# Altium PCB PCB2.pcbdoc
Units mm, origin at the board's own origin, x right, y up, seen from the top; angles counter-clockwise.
Board outline 165.99 x 69.13 mm, 2 copper layers (Top Layer, Bottom Layer); 50 components, 27 nets, 130 pads, 0 vias.
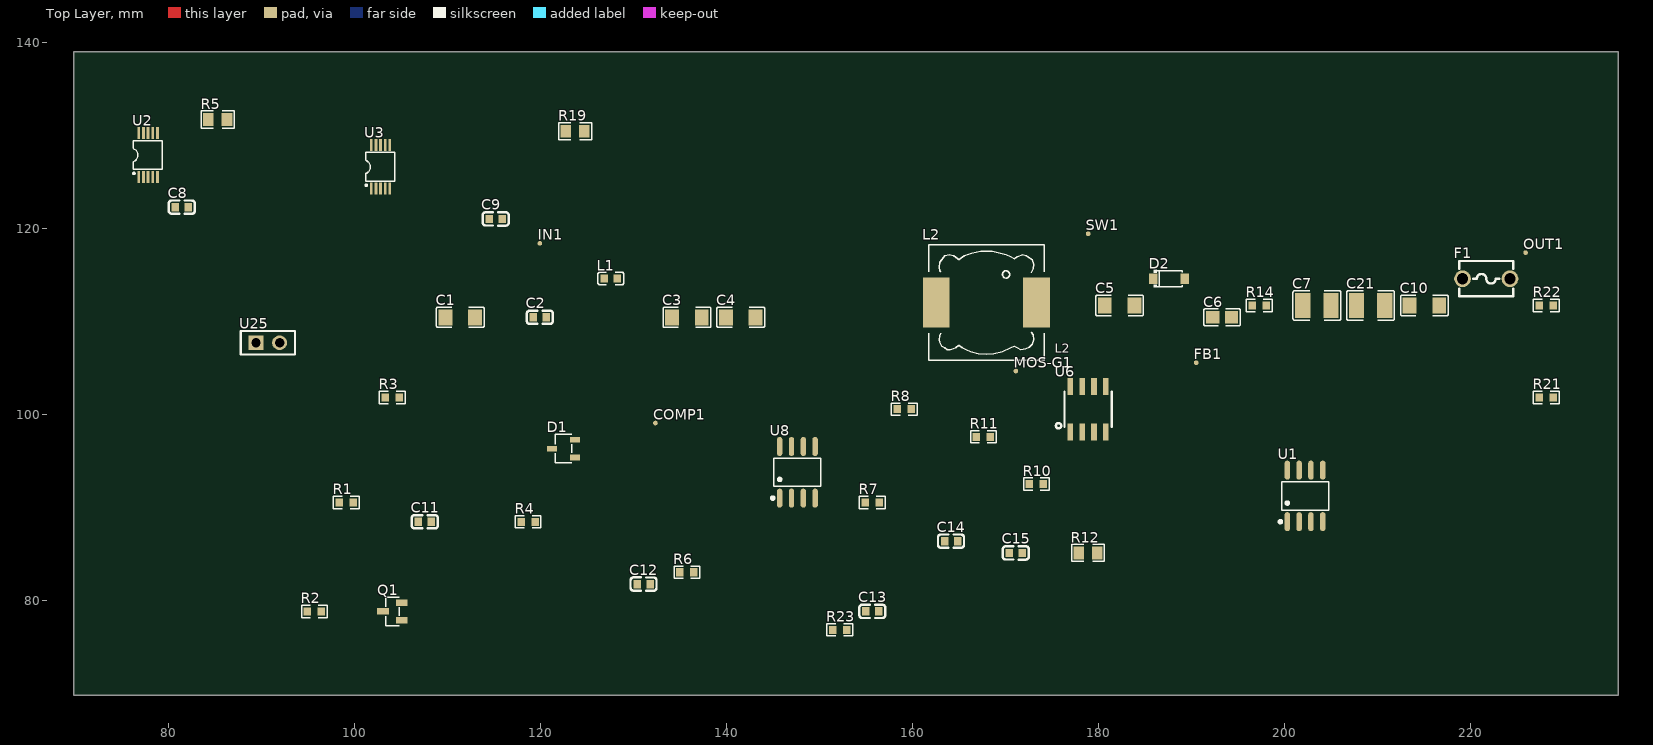
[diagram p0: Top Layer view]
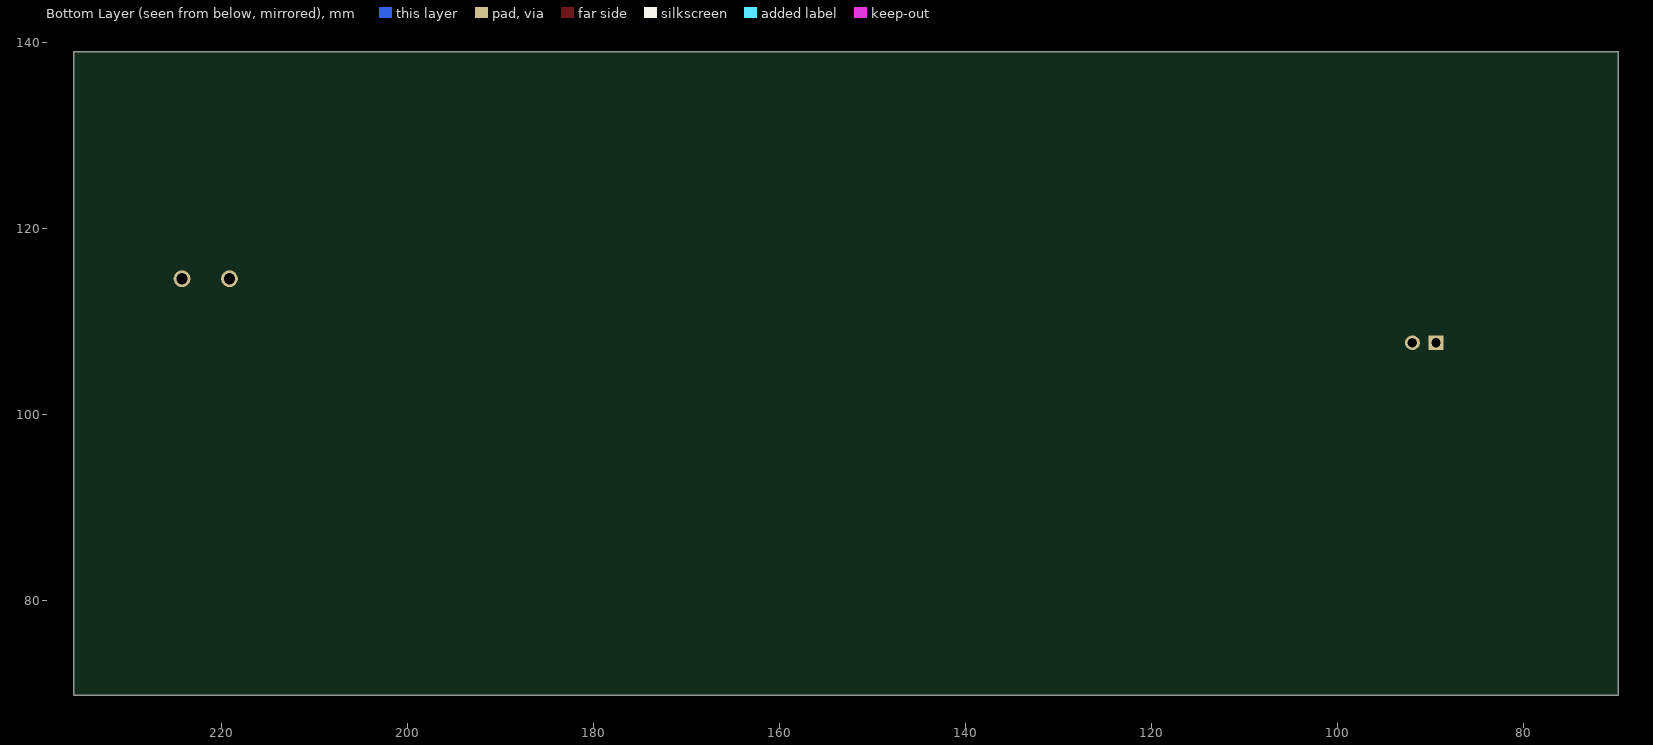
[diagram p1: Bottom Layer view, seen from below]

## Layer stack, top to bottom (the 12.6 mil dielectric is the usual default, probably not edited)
Top Layer: signal copper (thickness not stored)
Dielectric: dielectric 0.32, FR-4, Dk 4.8
Bottom Layer: signal copper (thickness not stored)

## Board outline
235.837,69.85 69.85,69.85 69.85,138.978 235.837,138.978

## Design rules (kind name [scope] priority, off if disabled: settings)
BoardOutlineClearance copperThickness1oz [All] p0: genericclearance=0.254 ignorepadtopadclearanceinfootprint=FALSE except(0: Arc-SplitContinuation Track-SplitContinuation SMDPad-SplitContinuation THPad-SplitContinuation Via-SplitContinuation Fill-SplitContinuation Poly-SplitContinuation Region-SplitContinuation Text-SplitContinuation; 0.152: SMDPad-CutoutEdge THPad-CutoutEdge Via-CutoutEdge Fill-CutoutEdge Region-CutoutEdge; 0.3: Track-OutlineEdge SMDPad-OutlineEdge THPad-OutlineEdge Via-OutlineEdge Fill-OutlineEdge Region-OutlineEdge Poly-OutlineEdge Text-OutlineEdge Track-CutoutEdge)
BoardOutlineClearance copperThickness2oz [All] p0: genericclearance=0.254 ignorepadtopadclearanceinfootprint=FALSE except(0: Arc-SplitContinuation Track-SplitContinuation SMDPad-SplitContinuation THPad-SplitContinuation Via-SplitContinuation Fill-SplitContinuation Poly-SplitContinuation Region-SplitContinuation Text-SplitContinuation; 0.152: SMDPad-CutoutEdge THPad-CutoutEdge Via-CutoutEdge Fill-CutoutEdge Region-CutoutEdge; 0.3: Track-OutlineEdge SMDPad-OutlineEdge THPad-OutlineEdge Via-OutlineEdge Fill-OutlineEdge Region-OutlineEdge Poly-OutlineEdge Text-OutlineEdge Track-CutoutEdge)
Clearance copperThickness1oz [(InNet('SPI_CS') OR InNet('SPI_CLK') OR InNet('SPI_SI') OR InNet('GND') OR InNet('5V') OR InNet('$1N3770') OR InNet('$1N3760') OR InNet('VBUS') OR InNet('170_GND') OR InNet('$1N2831') OR InNet('$1N2825') OR InNet('$1N2828') OR InNet('170V') OR InNet('$1N2851') OR InNet('$1N3400') OR InNet('$1N2845') OR InNet('$1N2846') OR InNet('$1N3681') OR InNet('$1N2823') OR InNet('$1N2833') OR InNet('$1N2832') OR InNet('$1N2815') OR InNet('$1N2826') OR InNet('POWER') OR InNet('17V') OR InNet('SDA') OR InNet('SCL'))] p1: gap=0.178 ignorepadtopadclearanceinfootprint=FALSE except(0.102: Track-Track; 0.152: Track-SMDPad SMDPad-SMDPad Track-THPad SMDPad-THPad THPad-THPad Track-Via SMDPad-Via THPad-Via Via-Via Track-Fill SMDPad-Fill THPad-Fill Via-Fill Fill-Fill SMDPad-Region THPad-Region Via-Region Fill-Region Region-Region Track-Poly SMDPad-Poly THPad-Poly Via-Poly Fill-Poly Poly-Poly Track-Text SMDPad-Text THPad-Text Via-Text Fill-Text Region-Text Poly-Text Text-Text Track-Hole SMDPad-Hole THPad-Hole Via-Hole Fill-Hole Region-Hole Poly-Hole Text-Hole; 0.3: Track-Region Region-Poly Track-Sheet SMDPad-Sheet THPad-Sheet Via-Sheet Fill-Sheet Region-Sheet Poly-Sheet Text-Sheet Sheet-Hole)
Clearance copperThickness2oz [All] p1: gap=0.178 ignorepadtopadclearanceinfootprint=FALSE except(0.152: Track-SMDPad SMDPad-SMDPad Track-THPad SMDPad-THPad THPad-THPad Track-Via SMDPad-Via THPad-Via Via-Via Track-Fill SMDPad-Fill THPad-Fill Via-Fill Fill-Fill SMDPad-Region THPad-Region Via-Region Fill-Region Region-Region Track-Poly SMDPad-Poly THPad-Poly Via-Poly Fill-Poly Poly-Poly Track-Text SMDPad-Text THPad-Text Via-Text Fill-Text Region-Text Poly-Text Text-Text Track-Hole SMDPad-Hole THPad-Hole Via-Hole Fill-Hole Region-Hole Poly-Hole Text-Hole; 0.203: Track-Track; 0.3: Track-Region Region-Poly Track-Sheet SMDPad-Sheet THPad-Sheet Via-Sheet Fill-Sheet Region-Sheet Poly-Sheet Text-Sheet Sheet-Hole)
DiffPairsRouting differentialPair [All] p1: maxuncoupledlength=10 minlimit=6 maxlimit=6 mostfreqgap=6 toplayer_minwidth=5 toplayer_prefwidth=10 toplayer_maxwidth=100 bottomlayer_minwidth=5 bottomlayer_prefwidth=10 bottomlayer_maxwidth=100
PasteMaskExpansion pasteMaskExpansion [All] p1: expansion=0
PlaneConnect innerPlane [All] p1: planeconnectstyle=Relief reliefexpansion=0.508 reliefentries=4 reliefconductorwidth=0.254 reliefairgap=0.254
PolygonConnect copperRegion [All] p1: connectstyle=Relief reliefentries=4 reliefconductorwidth=10 polygonreliefangle="90 Angle" airgapwidth=10
RoutingVias viaSize [All] p1: viastyle="Through Hole" holewidth=12.0078 minholewidth=11.811 maxholewidth=248.0314 width=24.0158 minwidth=19.685 maxwidth=393.7008
SolderMaskExpansion solderMaskExpansion [All] p1: useseparateexpansions=TRUE expansion=2 expansionbottom=2
Width copperThickness1oz [All] p1: maxlimit=100 minlimit=5 preferedwidth=10
Width copperThickness2oz [All] p1: maxlimit=100 minlimit=8 preferedwidth=10

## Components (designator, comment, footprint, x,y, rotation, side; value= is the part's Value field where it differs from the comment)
C1 "CC0805KRX7R9BB104" c1206 111.384,110.448 r0 top
C2 "CC0805KRX7R9BB104" c0603 119.942,110.448 r0 top
C3 "CC0805KRX7R9BB104" c1206 135.749,110.448 r0 top
C4 "CC0805KRX7R9BB104" c1206 141.529,110.448 r0 top
C5 "CC0805KRX7R9BB104" c1206 182.255,111.718 r0 top
C6 "CC0805KRX7R9BB104" C0805 193.269,110.448 r0 top
C7 "CC0805KRX7R9BB104" c1210 203.453,111.718 r0 top
C8 "0.1u" c0603 81.453,122.288 r0 top
C9 "0.1u" c0603 115.194,121.018 r0 top
C10 "CC0805KRX7R9BB104" c1206 215.012,111.718 r0 top
C11 "CC0805KRX7R9BB104" c0603 107.574,88.467 r0 top
C12 "CC0805KRX7R9BB104" c0603 131.089,81.774 r0 top
C13 "CC0805KRX7R9BB104" c0603 155.678,78.834 r0 top
C14 "CC0805KRX7R9BB104" c0603 164.134,86.387 r0 top
C15 "CC0805KRX7R9BB104" c0603 171.106,85.117 r0 top
C21 "CC0805KRX7R9BB104" c1210 209.233,111.718 r0 top
COMP1 "Test-Point" Test-Point-0.5mm 132.359,99.086 r0 top
D1 "BAT54C,215" SOT-23-3_L2.9-W1.6-P1.90-LS2.8-BR 122.462,96.33 r0 top
D2 "ES1J_C691230" sod-123_l2.7-w1.6-ls3.6-rd 187.562,114.6 r0 top
F1 "JK250-080U" FUSE-TH_L5.8-W3.8-P5.10-D0.8 221.665,114.6 r0 top
FB1 "Test-Point" Test-Point-0.5mm 190.479,105.567 r0 top
IN1 "Test-Point" Test-Point-0.5mm 119.942,118.402 r0 top
L1 "PZ3216D101-3R0TF" l0603 127.57,114.6 r0 top
L2 "CXP0630-330M-AG(33uh)" 33uh功率电感 167.944,112.052 r0 top
MOS-G1 "Test-Point" Test-Point-0.5mm 171.106,104.673 r0 top
OUT1 "Test-Point" Test-Point-0.5mm 225.89,117.402 r0 top
Q1 "MMBT5551_C2145" SOT-23-3_L2.9-W1.3-P1.90-LS2.4-BR 104.08,78.834 r0 top
R1 "0805W8F1002T5E_C17414" r0603 99.125,90.546 r0 top
R2 "0805W8F1002T5E_C17414" r0603 95.702,78.834 r0 top
R3 "0805W8F1002T5E_C17414" r0603 104.08,101.843 r0 top
R4 "0805W8F1002T5E_C17414" r0603 118.672,88.467 r0 top
R5 "10mΩ" R0805 85.308,131.711 r0 top
R6 "0805W8F1002T5E_C17414" r0603 135.749,83.044 r0 top
R7 "0805W8F1002T5E_C17414" r0603 155.678,90.546 r0 top
R8 "0805W8F1002T5E_C17414" r0603 159.1,100.573 r0 top
R10 "0805W8F1002T5E_C17414" r0603 173.318,92.52 r0 top
R11 "0805W8F1002T5E_C17414" r0603 167.613,97.6 r0 top
R12 "RL10FTNR160" R0805 178.865,85.117 r0 top
R14 "0805W8F1002T5E_C17414" r0603 197.27,111.718 r0 top
R19 "100mΩ" R0805 123.732,130.441 r0 top
R21 "0805W8F1002T5E_C17414" r0603 228.102,101.843 r0 top
R22 "0805W8F1002T5E_C17414" r0603 228.102,111.718 r0 top
R23 "0805W8F1002T5E_C17414" r0603 152.184,76.861 r0 top
SW1 "Test-Point" Test-Point-0.5mm 178.865,119.431 r0 top
U1 "MCP41010T-I/SN" SOIC-8_L4.9-W3.9-P1.27-LS6.0-BL 202.183,91.25 r0 top
U2 "INA220AIDGSR" VSSOP-10_L3.0-W3.0-P0.50-LS4.9-BL 77.824,127.901 r0 top
U3 "INA220AIDGSR" VSSOP-10_L3.0-W3.0-P0.50-LS4.9-BL 102.81,126.631 r0 top
U6 "FDS2672" SO-8_L4.9-W3.9-P1.27-LS6.0-BL 178.865,100.573 r0 top
U8 "UCC3803D" SOIC-8_L4.9-W3.9-P1.27-LS6.0-BL 147.62,93.79 r0 top
U25 "排针" 2.54mm1*2 90.693,107.714 r0 top

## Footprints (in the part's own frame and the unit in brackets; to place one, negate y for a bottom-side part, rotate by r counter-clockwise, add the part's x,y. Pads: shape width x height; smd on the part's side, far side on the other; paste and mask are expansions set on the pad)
2.54mm1*2 [mm]
  rect 1.6x1.6 hole 1: 1(-1.27,0)
  round 1.6 hole 1: 2(1.27,0)
  silkscreen extent -2.92,-1.27 2.92,1.27
33uh功率电感 [mm]
  rect 2.9x5.4 smd: 1(5.4,0) 2(-5.4,0)
  silkscreen extent -6.2,-6.2 6.2,6.2
c0603 [mm]
  rect 0.8x0.9 smd: 1(-0.7,0) 2(0.7,0)
  silkscreen extent -1.41,-0.71 1.39,0.72
C0805 [mm]
  rect 1.41x1.35 smd: 1(-1,0) 2(1,0)
  silkscreen extent -1.96,-0.9 1.96,0.9
c1206 [mm]
  rect 1.485x1.728 smd: 1(-1.593,0) 2(1.593,0)
  silkscreen extent -2.56,-1.09 2.56,1.09
c1210 [mm]
  rect 1.635x2.7 smd: 1(-1.517,0) 2(1.517,0)
  silkscreen extent -2.56,-1.58 2.56,1.58
FUSE-TH_L5.8-W3.8-P5.10-D0.8 [mm]
  round 1.8 hole 1.2: 1(-2.55,0) 2(2.55,0)
  silkscreen extent -2.9,-1.9 2.9,1.9
l0603 [mm]
  rect 0.8x0.864 smd: 1(-0.7,0) 2(0.7,0)
  silkscreen extent -1.42,-0.65 1.41,0.67
r0603 [mm]
  rect 0.806x0.864 smd: 1(-0.753,0) 2(0.753,0)
  silkscreen extent -1.39,-0.66 1.39,0.66
R0805 [mm]
  rect 1.133x1.377 smd: 1(-1,0) 2(1,0)
  silkscreen extent -1.76,-0.92 1.76,0.92
SO-8_L4.9-W3.9-P1.27-LS6.0-BL [mm]
  rect 0.6x1.8 smd: 1(-1.905,-2.45) 2(-0.635,-2.45) 3(0.635,-2.45) 4(1.905,-2.45) 5(1.905,2.45) 6(0.635,2.45) 7(-0.635,2.45) 8(-1.905,2.45)
  silkscreen extent -3.46,-2.06 2.54,1.91
sod-123_l2.7-w1.6-ls3.6-rd [mm]
  rect 0.95x1.15 smd: 1(-1.692,0) 2(1.692,0)
  silkscreen extent -1.63,-0.94 1.41,0.94
SOIC-8_L4.9-W3.9-P1.27-LS6.0-BL [mm]
  oval 0.588x2.045 smd: 1(-1.905,-2.772) 2(-0.635,-2.772) 3(0.635,-2.772) 4(1.905,-2.772) 5(1.905,2.772) 6(0.635,2.772) 7(-0.635,2.772) 8(-1.905,2.772)
  silkscreen extent -2.8,-2.92 2.53,1.52
SOT-23-3_L2.9-W1.3-P1.90-LS2.4-BR [mm]
  rect 1.25x0.7 smd: 1(1,-0.95) 2(1,0.95) 3(-1,0)
  silkscreen extent -0.73,-1.53 0.73,1.53
SOT-23-3_L2.9-W1.6-P1.90-LS2.8-BR [mm]
  rect 1.07x0.6 smd: 1(1.235,-0.95) 2(1.235,0.95) 3(-1.235,0)
  silkscreen extent -0.88,-1.54 0.88,1.54
Test-Point-0.5mm [mm]
  round 0.5 smd: 1(0,0)
VSSOP-10_L3.0-W3.0-P0.50-LS4.9-BL [mm]
  rect 0.3x1.3 smd: 1(-1,-2.35) 2(-0.5,-2.35) 3(0,-2.35) 4(0.5,-2.35) 5(1,-2.35) 6(1,2.35) 7(0.5,2.35) 8(0,2.35) 9(-0.5,2.35) 10(-1,2.35)
  silkscreen extent -1.62,-2.08 1.52,1.54

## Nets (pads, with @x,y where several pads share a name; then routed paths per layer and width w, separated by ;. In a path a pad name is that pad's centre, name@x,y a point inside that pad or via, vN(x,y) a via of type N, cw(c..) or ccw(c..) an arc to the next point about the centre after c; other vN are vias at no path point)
5V: C1.2 C2.2 C8.2 C9.2 IN1.1 L1.1 R1.2 R3.2 R5.1 U1.8 U2.6 U2.9 U3.1 U3.2 U3.6 U8.7
17V: R21.1 R22.2 U3.8
170_GND: R19.2 U3.10
170V: F1.2 OUT1.1 R22.1
$1N2815: Q1.1 R1.1 R2.1
$1N2823: C13.2 R7.1 U8.4
$1N2825: MOS-G1.1 R8.1 U6.4
$1N2826: R8.2 U8.6
$1N2828: C5.2 D2.2 L2.2 SW1.1 U6.5 U6.6 U6.7 U6.8
$1N2831: R10.1 R12.2 U6.1 U6.2 U6.3
$1N2832: C15.2 R10.2 R11.1 U8.3
$1N2833: C14.2 R7.2 R11.2 U8.8
$1N2845: C11.2 D1.3 Q1.3 R3.1 R4.2
$1N2846: C12.2 COMP1.1 D1.1 R6.2 U8.1
$1N2851: C3.2 C4.2 L1.2 L2.1
$1N3400: C6.2 C7.2 C10.2 C21.2 D2.1 F1.1 R14.2
$1N3681: C12.1 R6.1 R23.2 U8.2
$1N3760: R14.1 U1.5
$1N3770: C6.1 FB1.1 R23.1 U1.6
GND: C1.1 C2.1 C3.1 C4.1 C5.1 C7.1 C8.1 C9.1 C10.1 C11.1 C13.1 C14.1 C15.1 C21.1 Q1.2 R4.1 R12.1 R19.1 R21.2 U1.4 U1.7 U2.1 U2.2 U2.7 U3.7 U3.9 U8.5 U25.1
POWER: R2.2
SCL: U2.5 U3.5
SDA: U2.4 U3.4
SPI_CLK: U1.2
SPI_CS: U1.1
SPI_SI: U1.3
VBUS: R5.2 U2.8 U2.10 U25.2
pads on no net: D1.2 U2.3 U3.3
